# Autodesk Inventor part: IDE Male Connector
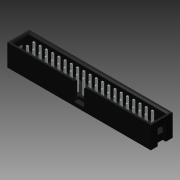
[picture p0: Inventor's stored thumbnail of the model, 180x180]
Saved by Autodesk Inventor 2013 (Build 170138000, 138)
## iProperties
Company: Autodesk Inc.
Created: 2005-12
Part Number: IDE Male Connector
Document SubType Name: Modeling
Designer: Autodesk Inc.
Density: 1 g/cm^3
Mass: 2.38693 g
Surface Area: 35.2874 cm^2
Volume: 2.38693 cm^3
Material: Allgemein
Title: Personal Computer
Author: Autodesk Inc.
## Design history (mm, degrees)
sketch "Sketch1"
  geometry: L1 (0, 6.223)-(0, -6.223) reference; L2 (-40.894, 0)-(40.894, 0) reference; L3 (-29.21, 4.445)-(29.21, 4.445); L4 (29.21, 4.445)-(29.21, -4.445); L5 (29.21, -4.445)-(-29.21, -4.445); L6 (-29.21, -4.445)-(-29.21, 4.445)
  constraints: 8 end point, 2 parallel, 1 horizontal, 1 perpendicular, 2 other
  dimensions: "d0" = 58.42 distance of L3.start L3.end; "d1" = 8.89 distance of L5.end L3.start
extrude "Extrusion1" new body sketch "Sketch1" distance "d2" = 8.89; taper "d3" = 0 deg
shell "Shell1" dims "d4" = 2.69, "d5" = 0.4, "d26" = 1.27, "d27" = 1.245
sketch "Sketch2"
  geometry: L1 (0, 8.89)-(0, 0) reference; L2 (-10.668, 4.445)-(1.778, 4.445) reference; L3 (-2.69, 7.645)-(-2.69, 1.245) reference; L4 (0, 6.096)-(-6.35, 6.096); L5 (-6.35, 6.096)-(-6.35, 2.794); L6 (-6.35, 2.794)-(0, 2.794); L7 (0, 2.794)-(0, 6.096)
  constraints: 8 end point, 2 parallel, 1 horizontal, 1 perpendicular, 1 point on line, 1 other
  dimensions: "d6" = 6.35 distance of L4.start L4.end; "d7" = 3.302 distance of L4.end L5.end
extrude "Extrusion2" cut sketch "Sketch2" stored distance "d8" = 9; taper "d9" = 0 deg
sketch "Sketch3"
  geometry: L1 (0, -8.89)-(58.42, -8.89) reference; L2 (29.21, 1.778)-(29.21, -10.668) reference; L3 (27.178, -8.89)-(31.242, -8.89); L4 (31.242, -8.89)-(31.242, -1.524); L5 (27.178, -1.524)-(27.178, -8.89); L6 (31.242, -1.524)-(27.178, -1.524)
  constraints: 8 end point, 2 perpendicular, 1 horizontal, 1 parallel, 1 point on line, 1 other
  dimensions: "d10" = 4.064 distance of L3.start L3.end; "d31" = 7.366 distance of L3.end L4.end
extrude "Extrusion3" cut sketch "Sketch3" distance "d16" = 1.778; taper "d17" = 0 deg
sketch "Sketch4"
  geometry: L1 (51.755, -1.57)-(52.385, -1.57); L2 (52.385, -1.57)-(52.385, -2.2); L3 (52.385, -2.2)-(51.755, -2.2); L4 (51.755, -2.2)-(51.755, -1.57); L5 (51.755, -4.2)-(52.385, -4.2); L6 (52.385, -4.2)-(52.385, -4.83); L7 (52.385, -4.83)-(51.755, -4.83); L8 (51.755, -4.83)-(51.755, -4.2); L9 (29.972, -0.533)-(25.908, -0.533) reference; L10 (55.88, -6.4)-(0, -6.4) reference; L11 (27.94, -6.4)-(27.94, -0.533); L12 (52.07, -2.2)-(52.07, -4.2)
  constraints: 20 end point, 4 midpoint, 4 parallel, 3 perpendicular, 2 collinear, 2 horizontal
  dimensions: "d18" = 0.63 distance of L1.start L1.end; "d32" = 48.26 diameter of L12 L11
extrude "Extrusion4" join sketch "Sketch4" distance "d21" = 6.1; taper "d22" = 0 deg
chamfer "Chamfer1" distance "d28" = 0.15; stored, may be unused: second distance "d29" = 2, angle "d30" = 45 deg
sketch "Sketch5"
  geometry: L1 (0, 0)-(0, 8.89) reference; L2 (0, 6.096)-(6.35, 6.096); L3 (6.35, 6.096)-(6.35, 2.794); L4 (6.35, 2.794)-(0, 2.794); L5 (0, 2.794)-(0, 6.096); 2 further points
  constraints: 8 end point, 2 midpoint, 2 parallel, 1 coincident, 1 horizontal, 1 perpendicular, 1 point on line
  dimensions: "d36" = 3.302 distance of L2.end L3.end; "d37" = 6.35 distance of L3.end L4.end
extrude "Extrusion5" cut sketch "Sketch5" stored distance "d38" = 10; taper "d39" = 0 deg
chamfer "Chamfer2" distance "d40" = 0.5; stored, may be unused: second distance "d41" = 2, angle "d42" = 45 deg
fillet "Fillet1" dims "d43" = 1
body "Solid1"
pattern_linear "Rectangular Pattern2" dims "d35" = 2.54
